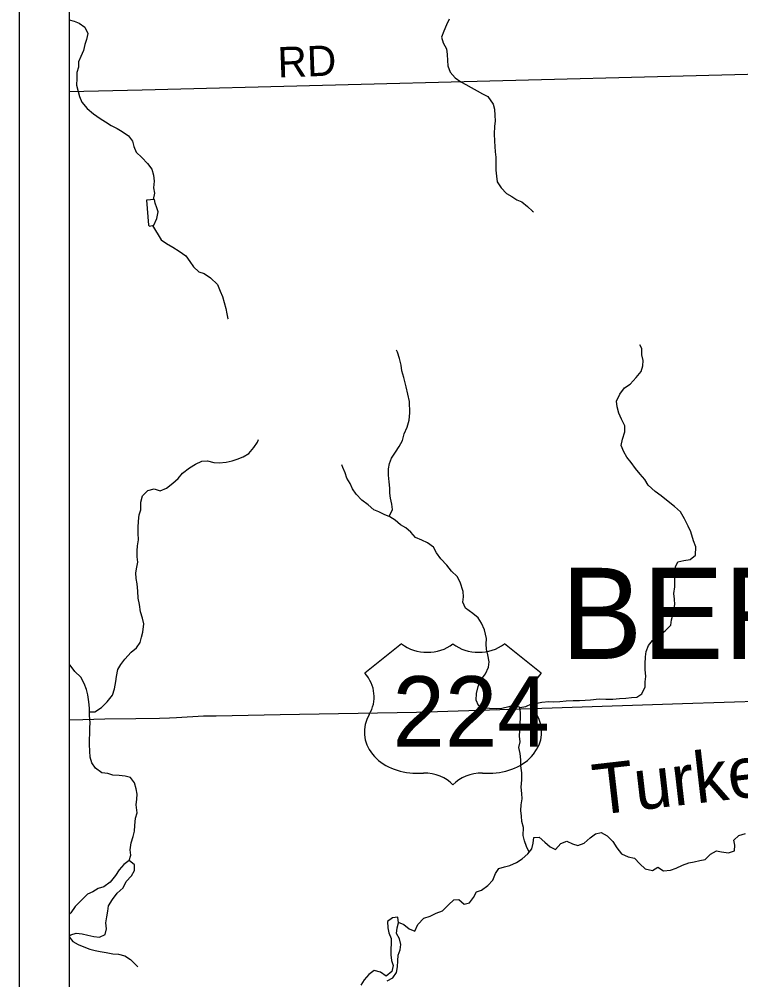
# Model space of a CAD drawing. Extents: x 0 to 34, y 0 to 22.
# Drawn here: x 2.63 to 3.98, y 12.758 to 14.555 of the extents above; entities that cross this region are included whole.
import ezdxf

# ---------------------------------------------------------------- set-up
doc = ezdxf.new("R2010")
doc.units = 0
for name, color, linetype in [('GM_X_Corporation', 7, 'Continuous'), ('GM_X_Major_Lake', 7, 'Continuous'), ('GM_X_Minor_Lake', 7, 'Continuous'), ('GM_X_Minor_River', 7, 'Continuous'), ('GM_X_Minor_River_Text', 7, 'Continuous'), ('GM_X_Township_Road', 7, 'Continuous'), ('GM_X_Township_Road_Text', 7, 'Continuous'), ('GM_X_Township_Text', 7, 'Continuous'), ('GM_X_US_Location', 7, 'Continuous'), ('GM_X_US_Route', 7, 'Continuous'), ('GM_X_US_Shield', 7, 'Continuous'), ('SH_Data', 7, 'Continuous')]:
    doc.layers.add(name, color=color, linetype=linetype)

msp = doc.modelspace()

# ---------------------------------------------------------------- linework, layer by layer
at = {"layer": 'GM_X_Corporation'}
msp.add_lwpolyline([(6.7217, 15.9197), (5.5749, 15.8972), (5.1967, 15.8898), (4.4889, 15.8766), (2.7231, 15.8419), (2.7231, 10.7149), (3.2181, 10.7269), (4.6326, 10.7519), (5.2789, 10.7635), (5.571, 10.7686), (6.8097, 10.7901)], dxfattribs=at)
at = {"layer": 'GM_X_Major_Lake'}
for points in [[(2.7231, 12.8402), (2.7264, 12.8425), (2.7362, 12.8453), (2.7476, 12.8442), (2.7579, 12.842), (2.7694, 12.8395), (2.7796, 12.8377), (2.7906, 12.8431), (2.7932, 12.8533), (2.792, 12.8651), (2.7938, 12.8762), (2.7952, 12.8868), (2.797, 12.8967), (2.8045, 12.9082), (2.8131, 12.9204), (2.8241, 12.93), (2.8301, 12.9422), (2.8399, 12.9529), (2.8451, 12.9629), (2.8454, 12.9731), (2.8354, 12.9814), (2.8256, 12.9737), (2.8166, 12.9641), (2.8098, 12.9535), (2.8, 12.9412), (2.7879, 12.932), (2.7773, 12.9289), (2.7675, 12.9231), (2.7576, 12.9184), (2.7467, 12.9077), (2.7346, 12.8955), (2.7264, 12.8836), (2.7231, 12.8801)], [(3.3185, 12.7564), (3.3288, 12.7618), (3.3359, 12.7722), (3.3377, 12.7824), (3.338, 12.7935), (3.3387, 12.8041), (3.3427, 12.814), (3.3438, 12.8243), (3.341, 12.8349), (3.3356, 12.8448), (3.3371, 12.8554), (3.3393, 12.8649), (3.338, 12.8756), (3.3285, 12.874), (3.3187, 12.8671), (3.3192, 12.8553), (3.3216, 12.8458), (3.3254, 12.8356), (3.3259, 12.8257), (3.3252, 12.8162), (3.325, 12.8048), (3.3266, 12.7941), (3.3293, 12.7847), (3.3267, 12.774), (3.3166, 12.7652), (3.3058, 12.7727), (3.294, 12.7756), (3.2842, 12.7683), (3.2752, 12.7584), (3.2688, 12.7481)]]:
    msp.add_lwpolyline(points, dxfattribs=at)
at = {"layer": 'GM_X_Minor_Lake'}
for points in [[(2.8717, 14.1699), (2.8736, 14.168), (2.8816, 14.17), (2.8872, 14.1826), (2.8897, 14.1952), (2.8874, 14.2027), (2.8843, 14.2115), (2.8831, 14.2183), (2.8679, 14.2167)], [(2.8679, 14.2167), (2.8717, 14.1699)]]:
    msp.add_lwpolyline(points, dxfattribs=at)
at = {"layer": 'GM_X_Minor_River'}
for points in [[(2.7231, 14.5544), (2.7322, 14.5516), (2.7421, 14.5482)], [(2.7421, 14.5482), (2.7524, 14.5407), (2.7582, 14.5286), (2.7557, 14.5176), (2.7527, 14.508), (2.7498, 14.497), (2.7449, 14.4859), (2.7404, 14.476), (2.7405, 14.4658), (2.7376, 14.4558), (2.7377, 14.4444), (2.7366, 14.4323), (2.7398, 14.4205), (2.7422, 14.411), (2.7468, 14.4), (2.7568, 14.3887), (2.7687, 14.3782), (2.7813, 14.3695), (2.7913, 14.3635), (2.8016, 14.3564), (2.8127, 14.3512), (2.8226, 14.3452), (2.8341, 14.3373), (2.8418, 14.3274), (2.8442, 14.3176), (2.8488, 14.3066), (2.8592, 14.2968), (2.8695, 14.2855), (2.8776, 14.2749), (2.8811, 14.2639), (2.882, 14.2525), (2.881, 14.2399), (2.8826, 14.2297), (2.8805, 14.218)], [(3.4342, 14.5557), (3.4294, 14.545), (3.4242, 14.5332), (3.4201, 14.5221), (3.4232, 14.5115), (3.429, 14.4998), (3.4306, 14.4892), (3.4311, 14.4781), (3.4316, 14.4683), (3.4363, 14.4565), (3.4455, 14.4459), (3.4558, 14.4384), (3.4657, 14.4332), (3.4753, 14.4279), (3.4864, 14.4216), (3.4963, 14.4159), (3.5066, 14.4111), (3.5163, 14.3963), (3.519, 14.3869), (3.5199, 14.3751), (3.5204, 14.3656), (3.5193, 14.3545), (3.5187, 14.3409), (3.5192, 14.3276), (3.5205, 14.3074), (3.5217, 14.2975), (3.5215, 14.2846), (3.5216, 14.2728), (3.5228, 14.2618), (3.524, 14.2512), (3.5317, 14.2399), (3.5417, 14.2293), (3.5513, 14.2237), (3.5608, 14.2173), (3.5704, 14.2136), (3.5807, 14.2053), (3.5903, 14.1962), (3.5918, 14.1951)], [(2.8789, 14.1693), (2.8951, 14.1424), (2.9055, 14.1356), (2.9173, 14.1292), (2.9292, 14.1214), (2.9414, 14.1127), (2.9491, 14.1021), (2.9557, 14.0923), (2.966, 14.0829), (2.976, 14.0795), (2.9874, 14.0716), (3.0005, 14.0592), (3.0059, 14.0467), (3.0102, 14.0369), (3.0129, 14.0255), (3.0161, 14.0141), (3.0181, 14.0042), (3.0201, 13.9947), (3.0193, 13.9951)], [(3.3219, 13.6252), (3.3279, 13.6384), (3.327, 13.6479), (3.3246, 13.6593), (3.3234, 13.6688), (3.3229, 13.6783), (3.3221, 13.69), (3.3208, 13.7022), (3.3207, 13.7144), (3.3225, 13.7243), (3.3266, 13.7342), (3.3341, 13.7452), (3.3409, 13.7563), (3.3469, 13.7674), (3.3502, 13.78), (3.3554, 13.7922), (3.3595, 13.8055), (3.3605, 13.8192), (3.3603, 13.8405), (3.3568, 13.8538), (3.3536, 13.8678), (3.3496, 13.8853), (3.3454, 13.8974), (3.3445, 13.9084), (3.3413, 13.9209), (3.3378, 13.9327), (3.3359, 13.9361)], [(3.5662, 13.2678), (3.5776, 13.2698), (3.5886, 13.2748), (3.5981, 13.276), (3.6079, 13.2776), (3.6205, 13.2789), (3.63, 13.2782), (3.6414, 13.279), (3.6532, 13.2799), (3.6665, 13.2808), (3.6783, 13.2805), (3.6889, 13.2813), (3.6984, 13.2821), (3.7151, 13.2838), (3.7277, 13.2831), (3.7406, 13.2836), (3.7532, 13.2845), (3.765, 13.285), (3.7752, 13.2862), (3.7851, 13.287), (3.7949, 13.2932), (3.8009, 13.3062), (3.8008, 13.3157), (3.8022, 13.3256), (3.801, 13.3389), (3.8009, 13.3495), (3.8015, 13.3624), (3.8026, 13.3727), (3.8071, 13.3838), (3.815, 13.3933), (3.8263, 13.4025), (3.8384, 13.4114), (3.8489, 13.4217), (3.8504, 13.4316), (3.853, 13.4411), (3.8544, 13.4507), (3.8562, 13.4602), (3.8557, 13.4704), (3.8549, 13.4811), (3.8563, 13.4932), (3.8566, 13.5054), (3.8561, 13.5206), (3.8579, 13.5309), (3.8623, 13.5404), (3.8734, 13.5428), (3.8855, 13.5448), (3.8953, 13.5529), (3.8956, 13.5684), (3.8913, 13.5794), (3.8862, 13.5961), (3.8812, 13.6067), (3.8746, 13.6207), (3.8668, 13.6336), (3.8557, 13.6438), (3.8439, 13.6532), (3.8312, 13.6637), (3.8194, 13.6716), (3.8067, 13.6837), (3.8001, 13.6943), (3.7917, 13.7045), (3.7832, 13.715), (3.7748, 13.726), (3.7667, 13.7358), (3.7613, 13.746), (3.7562, 13.7578), (3.7584, 13.7696), (3.7628, 13.7833), (3.7627, 13.7947), (3.7569, 13.8072), (3.7515, 13.8182), (3.7483, 13.8303), (3.7471, 13.8406), (3.7535, 13.8539), (3.7621, 13.8658), (3.7731, 13.8727), (3.7844, 13.885), (3.7934, 13.8964), (3.7967, 13.9071), (3.797, 13.917), (3.795, 13.9276), (3.7949, 13.9394), (3.7911, 13.9462)], [(2.7613, 13.2597), (2.771, 13.2599), (2.7835, 13.268), (2.794, 13.2783), (2.8042, 13.2906), (2.8082, 13.3024), (2.8104, 13.3165), (2.8115, 13.326), (2.8144, 13.3385), (2.82, 13.3481), (2.8275, 13.3584), (2.8392, 13.371), (2.849, 13.3791), (2.8558, 13.3894), (2.8584, 13.399), (2.8613, 13.4085), (2.8631, 13.4241), (2.8603, 13.4351), (2.8568, 13.4465), (2.8548, 13.4601), (2.852, 13.4723), (2.8519, 13.4856), (2.8502, 13.4992), (2.8483, 13.5091), (2.8478, 13.5197), (2.8496, 13.53), (2.8514, 13.5399), (2.8502, 13.5494), (2.8505, 13.5608), (2.8508, 13.5703), (2.8529, 13.5814), (2.8521, 13.5939), (2.852, 13.6042), (2.8526, 13.6163), (2.8544, 13.6281), (2.857, 13.6377), (2.8573, 13.6517), (2.8606, 13.6639), (2.8704, 13.6739), (2.8825, 13.6766), (2.8932, 13.6733), (2.9053, 13.678), (2.9174, 13.6875), (2.9272, 13.6964), (2.9351, 13.7059), (2.9484, 13.7159), (2.9597, 13.7232), (2.9715, 13.7283), (2.9817, 13.7291), (2.9939, 13.7262), (3.0038, 13.7255), (3.0171, 13.7267), (3.0281, 13.7295), (3.0376, 13.7326), (3.0486, 13.7369), (3.0592, 13.7427), (3.0686, 13.7541), (3.0757, 13.7641), (3.0772, 13.7694)], [(3.5838, 12.9972), (3.5788, 13.0075), (3.5752, 13.0181), (3.5729, 13.0284), (3.5731, 13.0432), (3.57, 13.0546), (3.5695, 13.0644), (3.5686, 13.0751), (3.5689, 13.0857), (3.5707, 13.0968), (3.5703, 13.107), (3.569, 13.1188), (3.5704, 13.1321), (3.5703, 13.1454), (3.5683, 13.1587), (3.5686, 13.1697), (3.5669, 13.1815), (3.5649, 13.1929), (3.5668, 13.2035), (3.5659, 13.2142), (3.5666, 13.2245), (3.5672, 13.237), (3.5675, 13.2488), (3.5678, 13.2583), (3.5662, 13.2678), (3.5559, 13.2723), (3.5456, 13.2691), (3.5327, 13.2656), (3.5225, 13.2651), (3.5099, 13.2658), (3.5, 13.2665), (3.4889, 13.2717), (3.4847, 13.2816), (3.4853, 13.2941), (3.4886, 13.3067), (3.4931, 13.3181), (3.5025, 13.3308), (3.5077, 13.343), (3.5088, 13.3532), (3.5067, 13.3661), (3.504, 13.3768), (3.5035, 13.3863), (3.5038, 13.3969), (3.5006, 13.4128), (3.4948, 13.4253), (3.4886, 13.4356), (3.4783, 13.4435), (3.4649, 13.4536), (3.4595, 13.465), (3.4609, 13.4749), (3.4604, 13.4847), (3.455, 13.5022), (3.4495, 13.5128), (3.4388, 13.523), (3.43, 13.5343), (3.4188, 13.546), (3.4104, 13.5573), (3.4049, 13.5675), (3.3938, 13.5758), (3.3831, 13.581), (3.3713, 13.5855), (3.3625, 13.5957), (3.3529, 13.604), (3.343, 13.6096), (3.3334, 13.6183), (3.3234, 13.6247), (3.3124, 13.6288), (3.3028, 13.634), (3.2933, 13.6377), (3.2829, 13.6468), (3.271, 13.6558), (3.2603, 13.6667), (3.2534, 13.6769), (3.2491, 13.6868), (3.2425, 13.697), (3.2398, 13.7069), (3.2355, 13.7167), (3.2336, 13.722)], [(2.8354, 12.9814), (2.8388, 12.9913), (2.8375, 13.0016), (2.8393, 13.0145), (2.8426, 13.0263), (2.8456, 13.0362), (2.8459, 13.0472), (2.8473, 13.0609), (2.8506, 13.0709), (2.8486, 13.0853), (2.85, 13.0959), (2.8503, 13.1058), (2.8483, 13.1153), (2.8452, 13.1267), (2.8379, 13.1369), (2.8279, 13.1395), (2.8165, 13.1405), (2.8051, 13.1412), (2.7956, 13.1442), (2.7845, 13.1456), (2.7723, 13.1542), (2.7654, 13.1641), (2.7626, 13.1747), (2.7617, 13.1857), (2.7612, 13.1982), (2.7615, 13.2085), (2.7618, 13.2184), (2.7617, 13.2294), (2.7624, 13.2393), (2.7611, 13.253), (2.7614, 13.2667), (2.7602, 13.2784), (2.7581, 13.2917), (2.7558, 13.3016), (2.7511, 13.3126), (2.7449, 13.3243), (2.7338, 13.3352), (2.7253, 13.347), (2.7231, 13.349)], [(3.3391, 12.866), (3.3496, 12.8616), (3.3595, 12.8533), (3.3702, 12.8492), (3.3758, 12.8614), (3.3867, 12.8737), (3.3985, 12.8772), (3.4098, 12.883), (3.4216, 12.8873), (3.4329, 12.8988), (3.4427, 12.9076), (3.4522, 12.9084), (3.4626, 12.8998), (3.4724, 12.9021), (3.4796, 12.9121), (3.4852, 12.9227), (3.4947, 12.9262), (3.5064, 12.9347), (3.5158, 12.9447), (3.521, 12.9569), (3.5274, 12.9664), (3.538, 12.9695), (3.5475, 12.9719), (3.5604, 12.9777), (3.571, 12.9843), (3.5812, 12.9938), (3.5887, 13.0034), (3.5916, 13.0141), (3.5927, 13.0243), (3.6029, 13.0252), (3.6133, 13.0158), (3.6233, 13.0067), (3.6332, 13.0019), (3.6434, 13.013), (3.6547, 13.0176), (3.665, 13.0128), (3.6753, 13.0098), (3.6871, 13.0137), (3.698, 13.024), (3.7079, 13.0313), (3.7185, 13.0337), (3.7299, 13.0277), (3.7403, 13.0168), (3.748, 13.0054), (3.7565, 12.9937), (3.7691, 12.9881), (3.7809, 12.9859), (3.7909, 12.9754), (3.8009, 12.966), (3.815, 12.963), (3.8248, 12.9692), (3.8351, 12.9624), (3.8484, 12.9633), (3.859, 12.9672), (3.8708, 12.973), (3.8825, 12.9773), (3.8924, 12.9792), (3.903, 12.9816), (3.9133, 12.9832), (3.9231, 12.9932), (3.9344, 12.9993), (3.944, 12.9979), (3.9569, 12.9957), (3.9679, 12.9996), (3.969, 13.0099), (3.9666, 13.0194), (3.9764, 13.0282), (3.9889, 13.0317)], [(2.7231, 12.8385), (2.7299, 12.8297), (2.7402, 12.824), (2.7509, 12.8199), (2.762, 12.8155), (2.7719, 12.8133), (2.7814, 12.8111), (2.7921, 12.8096), (2.8046, 12.8071), (2.8153, 12.8064), (2.8271, 12.8031), (2.8382, 12.7963), (2.8497, 12.7842), (2.8516, 12.7824)]]:
    msp.add_lwpolyline(points, dxfattribs=at)
at = {"layer": 'GM_X_Township_Road'}
msp.add_lwpolyline([(2.7231, 14.4203), (2.8599, 14.4232), (4.5468, 14.4668)], dxfattribs=at)
at = {"layer": 'GM_X_US_Route'}
for points in [[(2.9109, 13.2485), (2.9238, 13.249), (2.9744, 13.2518), (2.9981, 13.2523), (3.1177, 13.2545), (3.3733, 13.259), (3.6271, 13.2673), (3.8708, 13.2751), (4.183, 13.2852)], [(2.7231, 13.2444), (2.7485, 13.2453), (2.7902, 13.2464), (2.848, 13.247), (2.8919, 13.2479), (2.9109, 13.2485)]]:
    msp.add_lwpolyline(points, dxfattribs=at)
at = {"layer": 'GM_X_US_Shield'}
for p, q in [((3.3452, 13.3867), (3.2766, 13.3318)), ((3.6062, 13.3318), (3.5375, 13.3867)), ((3.3727, 13.145), (3.3864, 13.145)), ((3.4963, 13.145), (3.51, 13.145))]:
    msp.add_line(p, q, dxfattribs=at)
for centre, major_axis, start_param, end_param in [((3.3933, 13.4259), (-0.0687, 0), 0.795399, 2.346194), ((3.4894, 13.4259), (-0.0687, 0), 0.795399, 2.346194), ((3.1978, 13.2876), (0.0961, 0), 5.838949, 6.894067), ((3.6849, 13.2876), (-0.0961, 0), 5.672304, 6.727422), ((3.3716, 13.2219), (0.0961, 0), 2.702327, 4.723529), ((3.5111, 13.2219), (-0.0961, 0), 1.559657, 3.580859), ((3.3864, 13.0901), (-0.0687, 0), 3.785094, 4.712389), ((3.4963, 13.0901), (-0.0687, 0), 4.712389, 5.639684)]:
    msp.add_ellipse(centre, major_axis=major_axis, ratio=0.8, start_param=start_param, end_param=end_param, dxfattribs=at)
at = {"layer": 'SH_Data'}
msp.add_line((2.6297, 16.9017), (2.6297, 9.9017), dxfattribs=at)

# ---------------------------------------------------------------- texts
at = {"layer": 'GM_X_Minor_River_Text'}
msp.add_text('Turkey', height=0.09473, rotation=6.5592, dxfattribs=at).set_placement((3.7082, 13.0664))
at = {"layer": 'GM_X_Township_Road_Text'}
msp.add_text('RD', height=0.05682, rotation=1.9738, dxfattribs=at).set_placement((3.1141, 14.4464))
at = {"layer": 'GM_X_Township_Text'}
msp.add_text('BERLIN', height=0.17045, rotation=0, dxfattribs=at).set_placement((3.6436, 13.3586))
at = {"layer": 'GM_X_US_Location'}
for s in ['0', '/']:
    msp.add_text(s, height=0.000189, dxfattribs=at).set_placement((3.4415, 13.2602))
msp.add_text('224', height=0.000189, rotation=0, dxfattribs=at).set_placement((3.3832, 13.221))
at = {"layer": 'GM_X_US_Shield'}
msp.add_text('224', height=0.13184, dxfattribs=at).set_placement((3.3282, 13.1944))

doc.saveas('drawing.dxf')
